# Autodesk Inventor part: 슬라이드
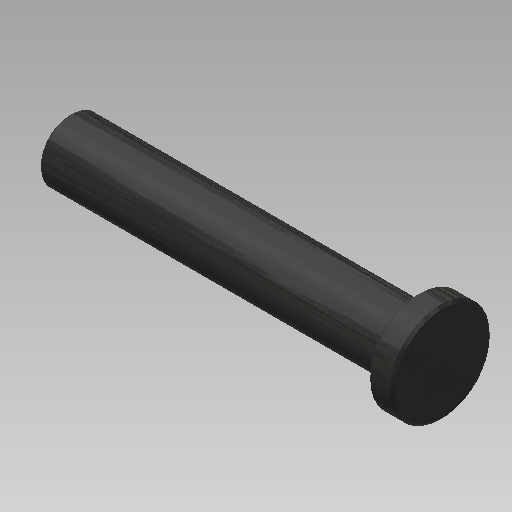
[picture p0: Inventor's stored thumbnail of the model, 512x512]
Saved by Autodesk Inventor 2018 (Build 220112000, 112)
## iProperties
Created: 2015-10
Part Number: 슬라이드
Document SubType Name: Modeling
Designer: mdu
Density: 1 g/cm^3
Material: 강철, 연강
Appearance: 진회색
Author: mdu
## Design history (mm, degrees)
sketch "스케치1"
  geometry: L1 (-75, 162)-(-75, 58) reference; L2 (-128, 110)-(22, 110); L3 (-128, 110)-(-128, 122.5); L4 (-128, 122.5)-(12, 122.5); L5 (12, 122.5)-(12, 130); L6 (12, 130)-(22, 130); L7 (22, 130)-(22, 110); 2 further points
  constraints: 12 end point, 3 parallel, 3 perpendicular, 1 midpoint, 1 point on line
  dimensions: "d0" = 40 diameter of L6 L2; "d1" = 25 diameter of L4 L2; "d2" = 10 distance of L5.end L6.end; "d3" = 150 distance of L2.start L2.end; "d4" = 53 distance between parallel lines of L3 L1
revolve "회전1" sketch "스케치1" stored, may be unused: angle "d5" = 90 deg
hole "구멍1" diameter "d11" = 10.106; stored, may be unused: countersink angle "d15" = 90 deg, drill point angle "d17" = 118 deg; dims "d12" = 22, "d13" = 4, "d14" = 2, "d16" = 25, "d18" = 10, "d19" = 10
chamfer "모따기1" distance "d6" = 1; stored, may be unused: second distance "d7" = 2, angle "d8" = 45 deg
node "솔리드1"
node "참조1"
